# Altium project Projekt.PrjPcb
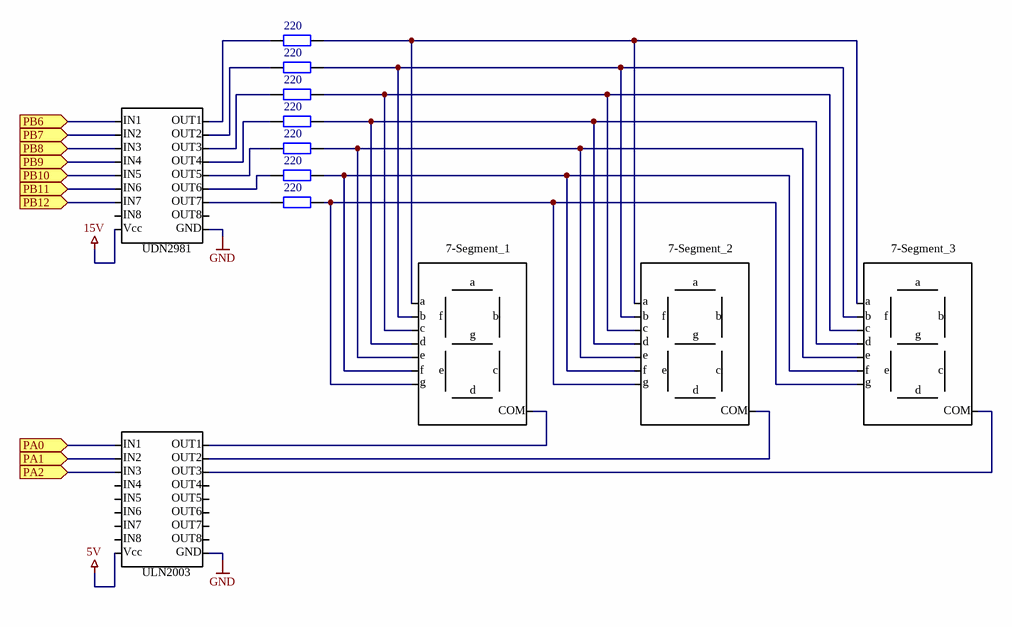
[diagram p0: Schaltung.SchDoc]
1 sheet, 7 parts. Net scope: flat (ports and power ports of the same name join across sheets).

## Sheet Schaltung.SchDoc
size A4; PageSetup: Record=PageOptions¦CenterHorizontal=True¦CenterVertical=True¦PrintScale=0.97¦XCorrection=1.00¦YCorrection=1.00¦PrintKind=2¦BorderSize=5000000¦LeftOffset=0¦BottomOffset=0¦Orientation=2¦PaperLength=1000¦PaperWidth=1000¦Scale=100¦PaperSource=7¦PrintQuality=-4¦MediaType=1¦DitherType=10¦PaperKind=A4¦PrintScaleMode=1

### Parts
R1  value 220  [AXIAL-0.4]  (hidden comment: Res2)
R2  value 220  [AXIAL-0.4]  (hidden comment: Res2)
R3  value 220  [AXIAL-0.4]  (hidden comment: Res2)
R4  value 220  [AXIAL-0.4]  (hidden comment: Res2)
R5  value 220  [AXIAL-0.4]  (hidden comment: Res2)
R6  value 220  [AXIAL-0.4]  (hidden comment: Res2)
R7  value 220  [AXIAL-0.4]  (hidden comment: Res2)

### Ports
PA0, PA1, PA2, PB6, PB7, PB8, PB9, PB10, PB11, PB12

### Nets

Not connected (* = marked no-connect by the designer): R1 1 2; R2 1 2; R3 1 2; R4 1 2; R5 1 2; R6 1 2; R7 1 2

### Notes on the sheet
- IN1
- IN2
- IN3
- IN4
- IN5
- IN6
- OUT1
- OUT2
- OUT3
- OUT4
- OUT5
- OUT6
- IN7
- IN8
- Vcc
- UDN2981
- OUT7
- OUT8
- GND
- 7-Segment_1
- 7-Segment_2
- 7-Segment_3
- a
- b
- f
- c
- d
- e
- g
- COM
- ULN2003

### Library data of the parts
R1-R7 = Res2: Resistor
